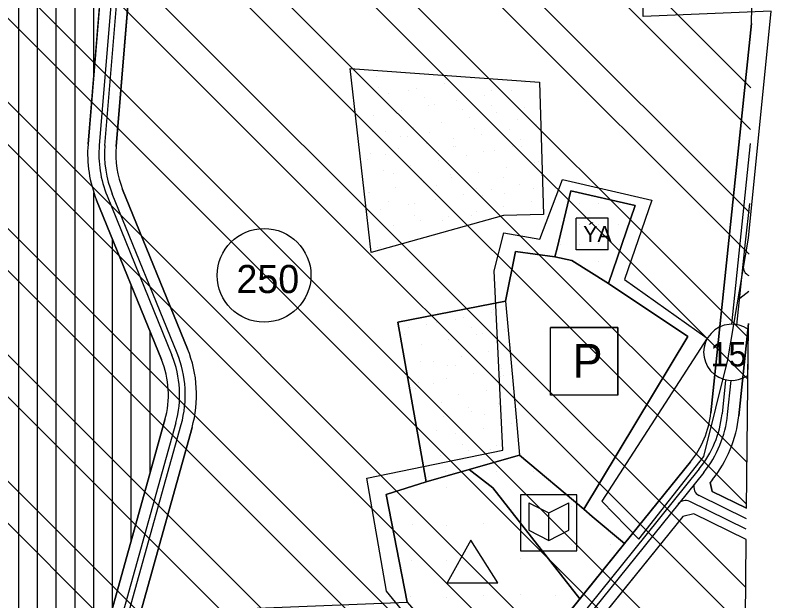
# Model space of a CAD drawing. Extents: x 409341 to 428634, y 4447481 to 4463281.
# Drawn here: x 420906.8 to 421316.4, y 4457848 to 4458160.3 of the extents above; entities that cross this region are included whole.
import ezdxf

# ---------------------------------------------------------------- set-up
doc = ezdxf.new("R2010")
doc.units = 0
for name, color, linetype in [('ADA', 7, 'Continuous'), ('ADAKENARI', 7, 'Continuous'), ('Default', 7, 'Continuous'), ('ILCE_ADLARI', 7, 'Continuous'), ('KALDIRIM', 7, 'Continuous'), ('KD_DAIRE', 7, 'Continuous'), ('KD_YGEN', 7, 'Continuous'), ('Level 21', 7, 'Continuous'), ('LJ_SEMBOL', 7, 'Continuous'), ('PL_AYA_PARK_DINLENME', 7, 'Continuous'), ('PL_EĞİTİM', 7, 'Continuous'), ('PL_K_PAZAR_ALANI', 7, 'Continuous'), ('PL_KON_MEV_250', 7, 'Continuous'), ('PL_KON_ONE_350', 7, 'Continuous'), ('PL_SAY_DINI_TESIS', 7, 'Continuous'), ('Plan Sembol', 7, 'Continuous'), ('SM_DAIRE', 7, 'Continuous'), ('SM_TAKS', 7, 'Continuous'), ('SN_TR_SIVILASMA', 7, 'Continuous'), ('TR_DINITESIS', 7, 'Continuous'), ('TR_EĞİTİM', 7, 'Continuous'), ('TR_KULTURELTESIS', 7, 'Continuous'), ('TR_ORTAGELISME', 7, 'Continuous'), ('TR_ORTAYOGUNKONUT', 7, 'Continuous'), ('TR_PARKALANI', 7, 'Continuous'), ('TR_PAZARLAMAAL', 7, 'Continuous')]:
    doc.layers.add(name, color=color, linetype=linetype)

# ---------------------------------------------------------------- blocks, each defined once
blk = doc.blocks.new('POINT_DISPLAY')
at = {"layer": 'Default'}
blk.add_line((0, 0), (0, 0), dxfattribs=at)
blk = doc.blocks.new('KULTUREL_TESIS_ALANI')
at = {"layer": 'TR_ORTAYOGUNKONUT'}
for p, q in [((150, 97.37547), (-150, 97.37547)), ((-150, 97.37547), (-150, -202.62453)), ((150, -202.62453), (150, 97.37547)), ((-106.920783, 54.47886), (0, 0)), ((-106.920783, 54.47886), (-106.920783, -92.13327)), ((0, 0), (106.920783, 54.47886)), ((106.920783, -92.13327), (106.920783, 54.47886)), ((0, -146.61213), (0, 0)), ((-106.920783, -92.13327), (0, -146.61213)), ((0, -146.61213), (106.920783, -92.13327)), ((-150, -202.62453), (150, -202.62453))]:
    blk.add_line(p, q, dxfattribs=at)
blk.add_lwpolyline([(-150, -202.62453), (150, -202.62453), (150, 97.37547), (-150, 97.37547)], close=True, dxfattribs=at)

msp = doc.modelspace()

# ---------------------------------------------------------------- linework, layer by layer
at = {"layer": 'ADA'}
for p, q in [((421085.24, 4458131.9), (421186.18, 4458124.57)), ((421096.52, 4458033.78), (421085.24, 4458131.9)), ((421186.18, 4458124.57), (421188.44, 4458054.08)), ((421188.44, 4458054.08), (421167.01, 4458053.52)), ((421167.01, 4458053.52), (421096.52, 4458033.78)), ((421173.36, 4458034.24), (421168.14, 4458007.84)), ((421195.6, 4458036.07), (421194.4, 4458031.48)), ((421168.14, 4458007.84), (421110.62, 4457996.56)), ((421168.14, 4458007.84), (421173.78, 4457945.81)), ((421110.62, 4457996.56), (421125.85, 4457911.41)), ((421125.85, 4457911.41), (421175.62, 4457925.59)), ((421125.85, 4457911.41), (421175.62, 4457925.59)), ((421125.85, 4457911.41), (421175.62, 4457925.59)), ((421175.62, 4457925.59), (421209.87, 4457896.75)), ((421125.85, 4457911.41), (421104.42, 4457904.65)), ((421104.42, 4457904.65), (421115.69, 4457847.13)), ((421209.87, 4457896.75), (421214.41, 4457892.92)), ((421214.41, 4457892.92), (421231.61, 4457878.44))]:
    msp.add_line(p, q, dxfattribs=at)
for points in [[(421195.6, 4458036.07), (421202.94, 4458066.69), (421237.29, 4458058.84), (421222.97, 4458017.27)], [(421209.89, 4457896.73), (421265.39, 4457988.9), (421222.97, 4458017.27), (421203.47, 4458029.51), (421194.4, 4458031.48), (421173.36, 4458034.24)], [(421148.7, 4457917.92), (421161.3, 4457908.23), (421207.76, 4457848.88)]]:
    msp.add_lwpolyline(points, dxfattribs=at)
at = {"layer": 'ADAKENARI'}
for p, q in [((420964.39, 4458319.42), (420945.51, 4458091.58)), ((420960.46, 4458090.34), (420979.33, 4458318.03)), ((421299.33, 4458155.94), (421277.6, 4457948.23)), ((420998.56, 4457982.3), (420963.97, 4458067.38)), ((420950.08, 4458061.73), (420984.67, 4457976.65)), ((421292.52, 4457946.67), (421297.66, 4457995.84)), ((420986.52, 4457944.4), (420940.52, 4457779.27)), ((420973.4, 4457841.41), (421000.97, 4457940.37)), ((421266.78, 4457922.04), (421231.61, 4457878.44)), ((421278.46, 4457912.62), (421277.22, 4457911.09)), ((421278.3, 4457906.22), (421277.22, 4457911.09)), ((421296.63, 4457897.26), (421278.3, 4457906.22)), ((421268.58, 4457894.28), (421262.59, 4457892.95)), ((421296.46, 4457880.64), (421268.58, 4457894.28)), ((421262.59, 4457892.95), (421168.94, 4457776.86)), ((421231.61, 4457878.44), (421162.95, 4457793.32)), ((421231.61, 4457878.44), (421162.95, 4457793.32)), ((421231.61, 4457878.44), (421162.95, 4457793.32))]:
    msp.add_line(p, q, dxfattribs=at)
for centre, radius, start, end in [((421010.29, 4458086.21), 65, 175.2626, 202.1263), ((421010.29, 4458086.21), 50, 175.2626, 202.1263), ((420938.35, 4457957.81), 65, 344.4354, 22.1263), ((420938.35, 4457957.81), 50, 344.4354, 22.1263), ((421227.87, 4457953.43), 50, 321.1061, 354.0263), ((421227.87, 4457953.43), 65, 321.1061, 354.0263), ((421227.87, 4457953.43), 65, 321.1061, 354.0263)]:
    msp.add_arc(centre, radius, start, end, dxfattribs=at)
at = {"layer": 'Default'}
msp.add_lwpolyline([(421050.15, 4457417.04), (421007.83, 4457463.42), (420944.65, 4457570.66), (421072.18, 4457668.63), (421162.04, 4457782.83), (421104.64, 4457852.98), (421094.21, 4457913.27), (421166.67, 4457928.34), (421162.04, 4458023.99), (421167.25, 4458044.28), (421186.38, 4458040.8), (421198.56, 4458072.69), (421246.09, 4458061.67), (421231.6, 4458019.35), (421275.66, 4457988.05), (421219.43, 4457901.09), (421239.14, 4457880.8), (421273.92, 4457924.86), (421286.67, 4457976.46), (421297.69, 4458041.38), (421309.86, 4458162.54), (421241.45, 4458159.64), (421240.3, 4458303.41)], dxfattribs=at)
at = {"layer": 'ILCE_ADLARI'}
msp.add_lwpolyline([(421209.89, 4457896.73), (421209.87, 4457896.75), (421175.62, 4457925.59), (421148.7, 4457917.92), (421161.3, 4457908.23), (421207.76, 4457848.88), (421231.61, 4457878.44), (421214.41, 4457892.92), (421209.89, 4457896.73)], dxfattribs=at)
at = {"layer": 'KALDIRIM'}
for p, q in [((420962, 4458217.92), (420951.49, 4458091.08)), ((420954.48, 4458090.83), (420965.01, 4458217.94)), ((421298.66, 4458091.9), (421288.58, 4457995.49)), ((420955.64, 4458063.99), (420990.23, 4457978.91)), ((420993.01, 4457980.04), (420958.41, 4458065.12)), ((421296.17, 4458039.22), (421298.33, 4458059.88)), ((421291.54, 4457995.01), (421296.17, 4458039.22)), ((421285.46, 4457965.68), (421283.56, 4457947.6)), ((421286.55, 4457947.29), (421288.46, 4457965.54)), ((420992.3, 4457942.79), (420961.36, 4457831.73)), ((420967.62, 4457843.02), (420995.19, 4457941.98)), ((421273.79, 4457916.39), (421207.69, 4457834.45)), ((421271.45, 4457918.27), (421236.28, 4457874.67)), ((421296.58, 4457891.72), (421271.31, 4457904.07)), ((421296.52, 4457886.18), (421266.33, 4457900.94)), ((421236.28, 4457874.67), (421205.77, 4457836.85))]:
    msp.add_line(p, q, dxfattribs=at)
msp.add_lwpolyline([(421293.05, 4458009.46), (421297.84, 4458013.19)], dxfattribs=at)
for centre, radius, start, end in [((421010.29, 4458086.21), 59, 175.2626, 202.1263), ((421010.29, 4458086.21), 56, 175.2626, 202.1263), ((421299.83, 4458026.14), 5, 174.0263, 247.7035), ((420938.35, 4457957.81), 56, 344.4354, 22.1263), ((420938.35, 4457957.81), 59, 344.4354, 22.1263), ((421227.87, 4457953.43), 56, 321.1061, 354.0263), ((421227.87, 4457953.43), 59, 321.1061, 354.0263), ((421273.51, 4457908.56), 5, 161.3066, 243.9467), ((421264.13, 4457896.45), 5, 63.9467, 141.1061)]:
    msp.add_arc(centre, radius, start, end, dxfattribs=at)
at = {"layer": 'KD_DAIRE'}
msp.add_line((421297.37, 4457968.2), (421297.63, 4457992.59), dxfattribs=at)
msp.add_arc((421288.77, 4457980.49), 15, 53.7916, 305.0127, dxfattribs=at)
at = {"layer": 'Level 21'}
for points in [[(421222.85, 4458052.1), (421205.85, 4458052.1)], [(421205.85, 4458035.1), (421205.85, 4458052.1)], [(421222.85, 4458035.1), (421222.85, 4458052.1)], [(421222.85, 4458035.1), (421205.85, 4458035.1)]]:
    msp.add_lwpolyline(points, dxfattribs=at)
at = {"layer": 'LJ_SEMBOL'}
for p, q in [((421149.57, 4457880.26), (421137.03, 4457857.45)), ((421164.05, 4457857.45), (421149.57, 4457880.26)), ((421137.03, 4457857.45), (421164.05, 4457857.45))]:
    msp.add_line(p, q, dxfattribs=at)
at = {"layer": 'PL_AYA_PARK_DINLENME'}
for points in [[(421096.52, 4458033.78), (421085.24, 4458131.9), (421186.18, 4458124.57), (421188.44, 4458054.08), (421167.01, 4458053.52)], [(421110.62, 4457996.56), (421168.14, 4458007.84), (421173.78, 4457945.81), (421175.62, 4457925.59), (421125.85, 4457911.41)]]:
    msp.add_lwpolyline(points, close=True, dxfattribs=at)
at = {"layer": 'PL_EĞİTİM'}
msp.add_lwpolyline([(421207.76, 4457848.88), (421161.3, 4457908.23), (421148.7, 4457917.92), (421125.85, 4457911.41), (421104.42, 4457904.65), (421115.69, 4457847.13), (421138.25, 4457821.19), (421138.82, 4457820.55), (421148.82, 4457809.27), (421150.6, 4457807.25), (421162.95, 4457793.32), (421207.76, 4457848.88)], dxfattribs=at)
at = {"layer": 'PL_K_PAZAR_ALANI'}
msp.add_lwpolyline([(421173.36, 4458034.24), (421168.14, 4458007.84), (421173.78, 4457945.81), (421175.62, 4457925.59), (421209.87, 4457896.75), (421209.89, 4457896.73), (421265.39, 4457988.9), (421222.97, 4458017.27), (421203.47, 4458029.51), (421194.4, 4458031.48), (421173.36, 4458034.24)], dxfattribs=at)
at = {"layer": 'PL_KON_MEV_250'}
for p, q in [((421299.33, 4458155.94), (421299.42, 4458164.61)), ((421277.6, 4457948.23), (421299.33, 4458155.94)), ((420963.97, 4458067.38), (420998.56, 4457982.3)), ((420984.67, 4457976.65), (420950.08, 4458061.73)), ((420940.52, 4457779.27), (420986.52, 4457944.4))]:
    msp.add_line(p, q, dxfattribs=at)
for points in [[(420945.51, 4458091.58), (420964.39, 4458319.42), (420964.54, 4458321.14), (420960.06, 4458327.14), (420932.35, 4458332.95)], [(421085.29, 4458300.89), (420988.83, 4458321.11), (420988.83, 4458315.56), (420979.14, 4458315.7), (420960.46, 4458090.34)], [(421188.44, 4458054.08), (421167.01, 4458053.52), (421096.52, 4458033.78), (421085.24, 4458131.9), (421186.18, 4458124.57), (421188.44, 4458054.08)], [(421000.97, 4457940.37), (420973.4, 4457841.41), (421115.69, 4457847.13), (421104.42, 4457904.65), (421125.85, 4457911.41), (421110.62, 4457996.56), (421168.14, 4458007.84), (421173.36, 4458034.24), (421194.4, 4458031.48), (421195.6, 4458036.07), (421202.94, 4458066.69), (421237.29, 4458058.84), (421222.97, 4458017.27), (421265.39, 4457988.9), (421209.89, 4457896.73), (421214.41, 4457892.92), (421231.61, 4457878.44), (421266.78, 4457922.04)]]:
    msp.add_lwpolyline(points, dxfattribs=at)
for centre, radius, start, end in [((421010.29, 4458086.21), 65, 175.2626, 202.1263), ((421010.29, 4458086.21), 50, 175.2626, 202.1263), ((420938.35, 4457957.81), 65, 344.4354, 22.1263), ((420938.35, 4457957.81), 50, 344.4354, 22.1263), ((421227.87, 4457953.43), 50, 321.1061, 354.0263)]:
    msp.add_arc(centre, radius, start, end, dxfattribs=at)
at = {"layer": 'PL_KON_ONE_350'}
for p, q in [((421297.66, 4457995.84), (421292.52, 4457946.67)), ((421296.63, 4457897.26), (421297.66, 4457995.84)), ((421295.4, 4457779.52), (421296.46, 4457880.64))]:
    msp.add_line(p, q, dxfattribs=at)
for points in [[(421278.46, 4457912.62), (421277.22, 4457911.09), (421278.3, 4457906.22), (421296.63, 4457897.26)], [(421296.46, 4457880.64), (421268.58, 4457894.28), (421262.59, 4457892.95), (421168.94, 4457776.86)]]:
    msp.add_lwpolyline(points, dxfattribs=at)
msp.add_arc((421227.87, 4457953.43), 65, 321.1061, 354.0263, dxfattribs=at)
at = {"layer": 'PL_SAY_DINI_TESIS'}
msp.add_lwpolyline([(421195.6, 4458036.07), (421194.4, 4458031.48), (421203.47, 4458029.51), (421222.97, 4458017.27), (421237.29, 4458058.84), (421202.94, 4458066.69), (421195.6, 4458036.07)], dxfattribs=at)
at = {"layer": 'Plan Sembol'}
for points in [[(421192.09, 4457957.71), (421192.09, 4457993.71)], [(421228.09, 4457993.71), (421192.09, 4457993.71)], [(421228.09, 4457957.71), (421228.09, 4457993.71)], [(421228.09, 4457957.71), (421192.09, 4457957.71)]]:
    msp.add_lwpolyline(points, dxfattribs=at)
at = {"layer": 'SM_DAIRE'}
msp.add_circle((421039.39, 4458021.55), 25, dxfattribs=at)
at = {"layer": 'SN_TR_SIVILASMA'}
for p, q in [((421298.05, 4458032.79), (420847.49, 4458483.35)), ((421297.58, 4457988.35), (420847.49, 4458438.45)), ((421297.35, 4457966.14), (420847.49, 4458416)), ((421298.97, 4458121.67), (421019.26, 4458401.39)), ((421298.28, 4458055.01), (420959.98, 4458393.31)), ((421298.74, 4458099.45), (421005.98, 4458392.22)), ((421296.89, 4457921.7), (420847.49, 4458371.1)), ((421296.66, 4457899.48), (420847.49, 4458348.64)), ((421296.19, 4457855.04), (420847.49, 4458303.74)), ((421295.96, 4457832.82), (420847.49, 4458281.29)), ((421295.5, 4457788.39), (420847.49, 4458236.39)), ((421285.81, 4457775.62), (420847.49, 4458213.94)), ((421240.43, 4457776.1), (420847.49, 4458169.04)), ((421217.74, 4457776.34), (420847.49, 4458146.59)), ((421013.52, 4457778.5), (420648.4, 4458143.63)), ((421036.21, 4457778.26), (420670.85, 4458143.63)), ((421149.66, 4457777.06), (420783.1, 4458143.63)), ((421172.36, 4457776.82), (420805.55, 4458143.63)), ((421104.28, 4457777.54), (420872.43, 4458009.39)), ((421081.59, 4457777.78), (420863.44, 4457995.94))]:
    msp.add_line(p, q, dxfattribs=at)
at = {"layer": 'TR_ORTAGELISME'}
for p, q in [((421297.66, 4457995.84), (421292.52, 4457946.67)), ((421296.63, 4457897.26), (421297.66, 4457995.84)), ((421295.4, 4457779.52), (421296.46, 4457880.64))]:
    msp.add_line(p, q, dxfattribs=at)
for points in [[(421278.46, 4457912.62), (421277.22, 4457911.09), (421278.3, 4457906.22), (421296.63, 4457897.26)], [(421296.46, 4457880.64), (421268.58, 4457894.28), (421262.59, 4457892.95), (421168.94, 4457776.86)]]:
    msp.add_lwpolyline(points, dxfattribs=at)
msp.add_arc((421227.87, 4457953.43), 65, 321.1061, 354.0263, dxfattribs=at)
at = {"layer": 'TR_ORTAYOGUNKONUT'}
for p, q in [((420908.59, 4457779.61), (420908.59, 4458334.88)), ((420918.59, 4457779.51), (420918.59, 4458334.8)), ((420928.59, 4457779.4), (420928.59, 4458333.66)), ((420938.59, 4457779.29), (420938.59, 4458331.65)), ((420948.59, 4458128.72), (420948.59, 4458329.55)), ((421299.33, 4458155.94), (421299.42, 4458164.61)), ((421277.6, 4457948.23), (421299.33, 4458155.94)), ((420963.97, 4458067.38), (420998.56, 4457982.3)), ((420948.59, 4457808.23), (420948.59, 4458065.76)), ((420958.59, 4457844.13), (420958.59, 4458040.79)), ((420968.59, 4457880.03), (420968.59, 4458016.19)), ((420978.59, 4457915.94), (420978.59, 4457991.6))]:
    msp.add_line(p, q, dxfattribs=at)
for points in [[(420945.51, 4458091.58), (420964.39, 4458319.42), (420964.54, 4458321.14), (420960.06, 4458327.14), (420932.35, 4458332.95)], [(421085.29, 4458300.89), (420988.83, 4458321.11), (420988.83, 4458315.56), (420979.14, 4458315.7), (420960.46, 4458090.34)], [(421186.18, 4458124.57), (421188.44, 4458054.08), (421167.01, 4458053.52), (421096.52, 4458033.78), (421085.24, 4458131.9), (421186.18, 4458124.57)], [(421000.97, 4457940.37), (420973.4, 4457841.41), (421115.69, 4457847.13), (421104.42, 4457904.65), (421125.85, 4457911.41), (421110.62, 4457996.56), (421168.14, 4458007.84), (421173.36, 4458034.24), (421194.4, 4458031.48), (421195.6, 4458036.07), (421202.94, 4458066.69), (421237.29, 4458058.84), (421222.97, 4458017.27), (421265.39, 4457988.9), (421209.89, 4457896.73), (421214.41, 4457892.92), (421231.61, 4457878.44), (421266.78, 4457922.04)], [(420984.67, 4457976.65), (420950.08, 4458061.73)], [(420940.52, 4457779.27), (420986.52, 4457944.4)]]:
    msp.add_lwpolyline(points, dxfattribs=at)
msp.add_circle((421039.39, 4458021.55), 25, dxfattribs=at)
for centre, radius, start, end in [((421010.29, 4458086.21), 65, 175.2626, 202.1263), ((421010.29, 4458086.21), 50, 175.2626, 202.1263), ((420938.35, 4457957.81), 65, 344.4354, 22.1263), ((420938.35, 4457957.81), 50, 344.4354, 22.1263), ((421227.87, 4457953.43), 50, 321.1061, 354.0263)]:
    msp.add_arc(centre, radius, start, end, dxfattribs=at)
at = {"layer": 'TR_PAZARLAMAAL'}
for points in [[(421222.97, 4458017.27), (421203.47, 4458029.51), (421194.4, 4458031.48), (421173.36, 4458034.24), (421168.14, 4458007.84), (421173.78, 4457945.81), (421175.62, 4457925.59), (421209.87, 4457896.75), (421209.89, 4457896.73), (421265.39, 4457988.9), (421222.97, 4458017.27)], [(421192.09, 4457993.71), (421228.09, 4457993.71), (421228.09, 4457957.71), (421192.09, 4457957.71), (421192.09, 4457993.71)]]:
    msp.add_lwpolyline(points, dxfattribs=at)

# ---------------------------------------------------------------- block references
at = {"layer": 'LJ_SEMBOL', "xscale": 0.1, "yscale": 0.10000000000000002}
msp.add_blockref('KULTUREL_TESIS_ALANI', (421191.17, 4457894.8), dxfattribs=at)
at = {"layer": 'TR_DINITESIS', "xscale": 0.1, "yscale": 0.10000000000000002}
for p in [(421207.31, 4458059.65), (421217.64, 4458059.84), (421228.28, 4458059.82), (421207.31, 4458048.47), (421217.64, 4458048.76), (421228.28, 4458048.63), (421197.55, 4458038.04), (421207.69, 4458038.04), (421217.64, 4458038.52), (421228.66, 4458038.21), (421207.63, 4458028.47), (421217.96, 4458028.75)]:
    msp.add_blockref('POINT_DISPLAY', p, dxfattribs=at)
at = {"layer": 'TR_EĞİTİM', "xscale": 0.1, "yscale": 0.10000000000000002}
for p in [(421136.67, 4457908.13), (421118.31, 4457888.44), (421136.67, 4457888.13), (421156.55, 4457889.11), (421156.55, 4457870.4), (421176.3, 4457870.62), (421117.86, 4457869.64), (421136.67, 4457869.41), (421117.72, 4457850.1), (421136.52, 4457849.87), (421156.4, 4457850.86), (421176.15, 4457851.08), (421194.96, 4457850.86)]:
    msp.add_blockref('POINT_DISPLAY', p, dxfattribs=at)
at = {"layer": 'TR_KULTURELTESIS', "xscale": 0.1, "yscale": 0.10000000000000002}
for p in [(421163.13, 4457916.76), (421183.13, 4457916.76), (421183.13, 4457898.15), (421203.13, 4457898.15), (421183.13, 4457878.15), (421203.13, 4457878.15), (421224.18, 4457878.15), (421203.13, 4457858.15)]:
    msp.add_blockref('POINT_DISPLAY', p, dxfattribs=at)
at = {"layer": 'TR_PARKALANI', "xscale": 0.1, "yscale": 0.10000000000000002}
for p in [(421099.16, 4458127.62), (421099.16, 4458127.62), (421135.36, 4458123.85), (421135.36, 4458123.85), (421136.21, 4458125.97), (421150.14, 4458126.46), (421150.14, 4458126.46), (421178, 4458124.54), (421100.37, 4458122.01), (421116.3, 4458120.19), (421120.59, 4458121.25), (421120.59, 4458121.25), (421160.56, 4458120.29), (421160.56, 4458120.29), (421171.57, 4458120.08), (421171.57, 4458120.08), (421100.66, 4458117.87), (421105.82, 4458118.64), (421105.82, 4458118.64), (421124.72, 4458116.33), (421124.72, 4458116.33), (421156.8, 4458117.48), (421156.8, 4458117.48), (421127.25, 4458112.27), (421127.25, 4458112.27), (421130.21, 4458112.66), (421142.02, 4458114.87), (421142.02, 4458114.87), (421160.62, 4458112.37), (421112.48, 4458109.66), (421112.48, 4458109.66), (421144.98, 4458110.06), (421163.46, 4458108.5), (421163.46, 4458108.5), (421178.23, 4458111.1), (421178.23, 4458111.1), (421097.71, 4458107.06), (421097.71, 4458107.06), (421133.91, 4458103.29), (421133.91, 4458103.29), (421148.69, 4458105.89), (421148.69, 4458105.89), (421174.52, 4458104.85), (421119.14, 4458100.68), (421119.14, 4458100.68), (421151.66, 4458099.78), (421170.12, 4458099.52), (421170.12, 4458099.52), (421184.89, 4458102.12), (421184.89, 4458102.12), (421097.19, 4458098.17), (421104.37, 4458098.08), (421104.37, 4458098.08), (421111.96, 4458095.57), (421115.83, 4458095.81), (421127.6, 4458097.89), (421155.35, 4458096.91), (421155.35, 4458096.91), (421125.8, 4458091.7), (421125.8, 4458091.7), (421140.57, 4458094.31), (421140.57, 4458094.31), (421176.01, 4458094.1), (421176.01, 4458094.1), (421111.03, 4458089.1), (421111.03, 4458089.1), (421140.17, 4458090.13), (421140.17, 4458090.13), (421141.51, 4458090.36), (421156.28, 4458087.75), (421162.01, 4458087.93), (421162.01, 4458087.93), (421171.92, 4458090.07), (421176.78, 4458090.54), (421176.78, 4458090.54), (421094.58, 4458083.4), (421096.26, 4458086.49), (421096.26, 4458086.49), (421104.34, 4458086.17), (421104.34, 4458086.17), (421132.46, 4458082.72), (421132.46, 4458082.72), (421147.23, 4458085.33), (421147.23, 4458085.33), (421117.69, 4458080.12), (421117.69, 4458080.12), (421168.67, 4458078.95), (421168.67, 4458078.95), (421183.44, 4458081.56), (421183.44, 4458081.56), (421185.82, 4458082.54), (421102.92, 4458077.51), (421102.92, 4458077.51), (421108.49, 4458075.87), (421138.9, 4458075.59), (421153.89, 4458076.35), (421153.89, 4458076.35), (421123.26, 4458073.27), (421124.35, 4458071.14), (421124.35, 4458071.14), (421139.12, 4458073.74), (421139.12, 4458073.74), (421167.12, 4458073.58), (421109.58, 4458068.53), (421109.58, 4458068.53), (421131.28, 4458069.62), (421152.81, 4458068.06), (421160.56, 4458067.37), (421160.56, 4458067.37), (421175.33, 4458069.97), (421175.33, 4458069.97), (421183.22, 4458067.77), (421094.81, 4458065.93), (421094.81, 4458065.93), (421095.44, 4458065.66), (421145.78, 4458064.76), (421145.78, 4458064.76), (421155.63, 4458063.94), (421155.63, 4458063.94), (421167.58, 4458065.45), (421105.88, 4458061.1), (421116.24, 4458059.55), (421116.24, 4458059.55), (421119.79, 4458059.98), (421119.79, 4458059.98), (421131.01, 4458062.16), (421131.01, 4458062.16), (421167.22, 4458058.39), (421167.22, 4458058.39), (421181.99, 4458060.99), (421181.99, 4458060.99), (421101.47, 4458056.95), (421101.47, 4458056.95), (421152.44, 4458055.78), (421152.44, 4458055.78), (421119.79, 4458053.57), (421122.9, 4458050.57), (421122.9, 4458050.57), (421134.56, 4458050.97), (421137.67, 4458053.18), (421137.67, 4458053.18), (421150.2, 4458053.29), (421108.13, 4458047.97), (421108.13, 4458047.97), (421110.9, 4458039.46), (421114.79, 4458038.99), (421114.79, 4458038.99), (421100.02, 4458036.39), (421100.02, 4458036.39), (421101.54, 4458036.48), (421160.74, 4458001.48), (421160.74, 4458001.48), (421161.59, 4458003.6), (421141.68, 4457997.82), (421145.97, 4457998.88), (421145.97, 4457998.88), (421116.42, 4457993.67), (421116.42, 4457993.67), (421126.04, 4457995.5), (421131.2, 4457996.27), (421131.2, 4457996.27), (421150.1, 4457993.96), (421150.1, 4457993.96), (421114.26, 4457990), (421114.26, 4457990), (421152.63, 4457989.9), (421152.63, 4457989.9), (421155.58, 4457990.29), (421167.4, 4457992.5), (421167.4, 4457992.5), (421123.08, 4457984.69), (421123.08, 4457984.69), (421137.86, 4457987.29), (421137.86, 4457987.29), (421159.29, 4457980.92), (421159.29, 4457980.92), (421144.52, 4457978.31), (421144.52, 4457978.31), (421114.97, 4457973.11), (421114.97, 4457973.11), (421122.57, 4457975.8), (421129.75, 4457975.71), (421129.75, 4457975.71), (421137.34, 4457973.2), (421141.2, 4457973.44), (421152.98, 4457975.52), (421151.18, 4457969.33), (421151.18, 4457969.33), (421165.95, 4457971.94), (421165.95, 4457971.94), (421121.63, 4457964.13), (421121.63, 4457964.13), (421136.41, 4457966.73), (421136.41, 4457966.73), (421165.55, 4457967.77), (421165.55, 4457967.77), (421166.88, 4457967.99), (421119.96, 4457961.03), (421129.71, 4457963.8), (421129.71, 4457963.8), (421157.84, 4457960.36), (421157.84, 4457960.36), (421143.07, 4457957.75), (421143.07, 4457957.75), (421128.29, 4457955.15), (421128.29, 4457955.15), (421133.86, 4457953.5), (421164.28, 4457953.22), (421148.64, 4457950.9), (421149.73, 4457948.77), (421149.73, 4457948.77), (421164.5, 4457951.38), (421164.5, 4457951.38), (421120.18, 4457943.56), (421120.18, 4457943.56), (421134.95, 4457946.17), (421134.95, 4457946.17), (421156.66, 4457947.25), (421120.82, 4457943.29), (421156.39, 4457939.79), (421156.39, 4457939.79), (421171.16, 4457942.4), (421171.16, 4457942.4), (421131.26, 4457938.73), (421141.62, 4457937.19), (421141.62, 4457937.19), (421145.17, 4457937.61), (421145.17, 4457937.61), (421126.84, 4457934.58), (421126.84, 4457934.58), (421145.16, 4457931.2), (421148.28, 4457928.21), (421148.28, 4457928.21), (421159.94, 4457928.6), (421163.05, 4457930.81), (421163.05, 4457930.81), (421133.5, 4457925.6), (421133.5, 4457925.6), (421136.27, 4457917.09), (421140.16, 4457916.62), (421140.16, 4457916.62), (421140.16, 4457916.62), (421140.16, 4457916.62), (421142.56, 4457916.43), (421142.56, 4457916.43), (421125.39, 4457914.02), (421125.39, 4457914.02), (421126.92, 4457914.11), (421126.92, 4457914.11)]:
    msp.add_blockref('POINT_DISPLAY', p, dxfattribs=at)

# ---------------------------------------------------------------- texts
at = {"layer": 'Default'}
for s, p in [('18.10.2018 TARİHLİ KARARI İLE YÜRÜTMESİ DURDURULMUŞTUR. (BBMK: 28.12.2018/2840)', (421256.46, 4457501.97)), ("BURSA 1. İDARE MAHKEMESİ'NİN 2017/849 E. SAYI VE ", (421293.63, 4457678.34))]:
    msp.add_text(s, height=15, rotation=70.3879, dxfattribs=at).set_placement(p)
at = {"layer": 'KD_YGEN'}
msp.add_text('15', height=13, dxfattribs=at).set_placement((421277.35, 4457972.95))
at = {"layer": 'Level 21'}
msp.add_text('ÝA', height=8.5, dxfattribs=at).set_placement((421209.54, 4458039.36))
at = {"layer": 'Plan Sembol'}
msp.add_text('P', height=18, dxfattribs=at).set_placement((421203.83, 4457966.99))
at = {"layer": 'SM_TAKS'}
msp.add_text('250', height=15, dxfattribs=at).set_placement((421024.65, 4458012.1))

doc.saveas('drawing.dxf')
